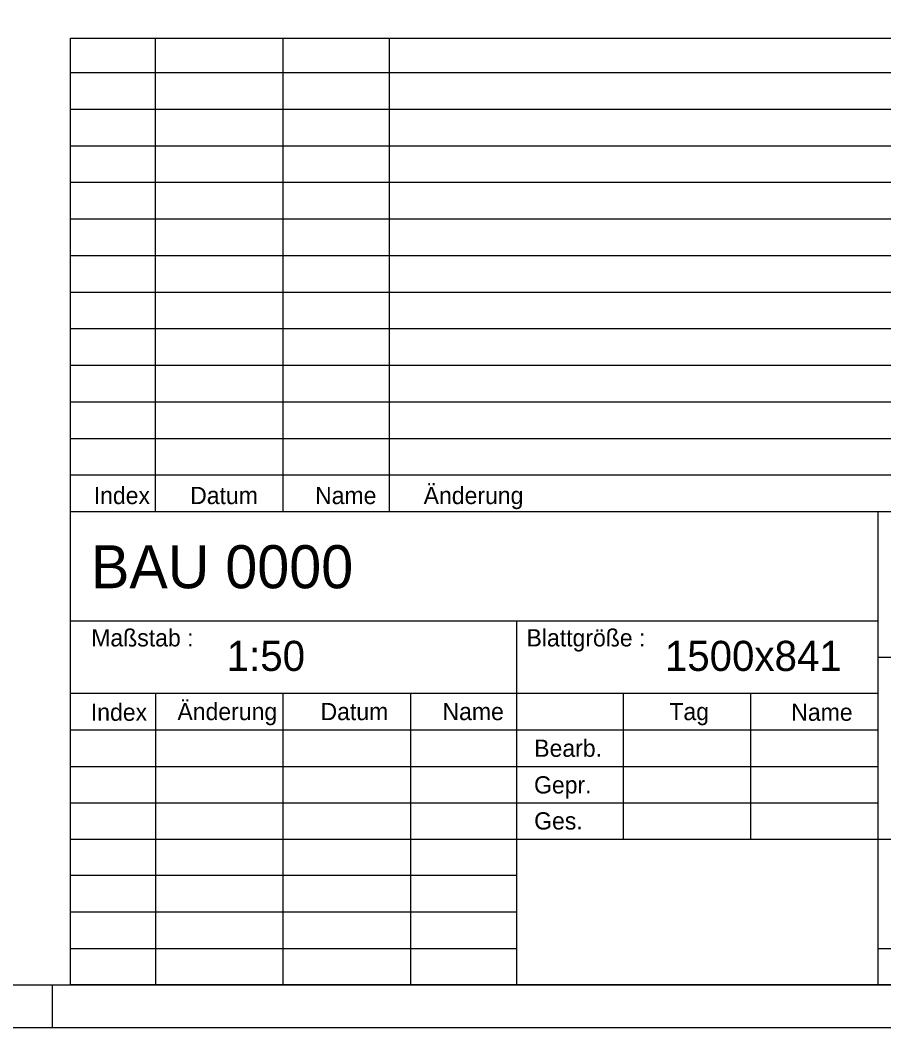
# Model space of a CAD drawing. Extents: x 0 to 75, y 0 to 42.1.
# Drawn here: x 65.56 to 70.58, y 0 to 5.85 of the extents above; entities that cross this region are included whole.
import ezdxf

# ---------------------------------------------------------------- set-up
doc = ezdxf.new("R2010")
doc.units = 0
doc.layers.add('90_Plankopf', color=7, linetype='Continuous')

msp = doc.modelspace()

# ---------------------------------------------------------------- linework, layer by layer
at = {"layer": '90_Plankopf'}
for p, q in [((65.856, 2.9995), (65.856, 5.749)), ((65.856, 5.749), (74.75, 5.749)), ((66.3501, 2.9995), (66.3501, 5.749)), ((67.0913, 2.9995), (67.0913, 5.749)), ((67.709, 2.9995), (67.709, 5.749)), ((65.856, 5.5495), (74.75, 5.5495)), ((65.856, 5.337), (74.75, 5.337)), ((65.856, 5.1245), (74.75, 5.1245)), ((65.856, 4.912), (74.75, 4.912)), ((65.856, 4.6995), (74.75, 4.6995)), ((65.856, 4.487), (74.75, 4.487)), ((65.856, 4.2745), (74.75, 4.2745)), ((65.856, 4.062), (74.75, 4.062)), ((65.856, 3.8495), (74.75, 3.8495)), ((65.856, 3.637), (74.75, 3.637)), ((65.856, 3.4245), (74.75, 3.4245)), ((65.856, 3.212), (74.75, 3.212)), ((65.856, 2.9995), (74.75, 2.9995)), ((65.856, 0.25), (65.856, 2.9995)), ((65.856, 2.9995), (74.75, 2.9995)), ((70.55, 0.25), (70.55, 2.9995)), ((65.856, 2.365), (70.55, 2.365)), ((68.4501, 0.25), (68.4501, 2.365)), ((70.55, 2.1535), (74.75, 2.1535)), ((65.856, 1.9435), (70.55, 1.9435)), ((66.3501, 1.942), (66.3501, 0.25)), ((67.0913, 0.25), (67.0913, 1.942)), ((67.8325, 0.25), (67.8325, 1.942)), ((69.0677, 1.942), (69.0677, 1.096)), ((69.8089, 1.096), (69.8089, 1.942)), ((65.856, 1.7315), (70.55, 1.7315)), ((65.856, 1.519), (70.55, 1.519)), ((65.856, 1.3075), (70.55, 1.3075)), ((65.856, 1.096), (70.55, 1.096)), ((65.856, 1.096), (70.55, 1.096)), ((68.4501, 1.096), (70.55, 1.096)), ((70.55, 1.096), (74.75, 1.096)), ((68.4501, 0.8845), (65.856, 0.8845)), ((68.4501, 0.673), (65.856, 0.673)), ((65.856, 0.4615), (68.4501, 0.4615)), ((70.55, 0.4615), (74.75, 0.4615)), ((65.75, 0), (65.75, 0.25)), ((74.75, 0.25), (65.856, 0.25)), ((65.856, 0.25), (68.4501, 0.25)), ((66.44, 0.25), (74.75, 0.25)), ((66.44, 0.25), (74.75, 0.25))]:
    msp.add_line(p, q, dxfattribs=at)
msp.add_lwpolyline([(0, 42.05), (75, 42.05), (75, 0), (0, 0)], close=True, dxfattribs=at)
msp.add_lwpolyline([(59.6038, 0.25), (74.75, 0.25), (74.75, 41.8), (59.6038, 41.8)], dxfattribs=at)

# ---------------------------------------------------------------- texts
for s, height, p in [('Änderung', 0.1, (67.9079, 3.0428)), ('Index', 0.1, (65.9902, 3.0428)), ('Datum', 0.1, (66.5507, 3.0428)), ('Name', 0.1, (67.2769, 3.0428)), ('BAU 0000      ', 0.25, (65.9745, 2.5538)), ('Maßstab :', 0.1, (65.9758, 2.2158)), ('Blattgröße :', 0.099995, (68.5058, 2.2158)), ('1:50     ', 0.175, (66.7631, 2.0734)), ('1500x841 ', 0.175, (69.31, 2.0734)), ('Index', 0.1, (65.9734, 1.7837)), ('Änderung', 0.1, (66.4767, 1.7875)), ('Datum', 0.1, (67.3084, 1.7875)), ('Name', 0.1, (68.0174, 1.7875)), ('Tag', 0.1, (69.3362, 1.7875)), ('Name', 0.1, (70.0446, 1.7837)), ('Bearb.', 0.1, (68.5507, 1.5745)), ('Gepr.', 0.1, (68.5495, 1.3615)), ('Ges.', 0.1, (68.5502, 1.1523))]:
    msp.add_text(s, height=height, dxfattribs=at).set_placement(p)

doc.saveas('drawing.dxf')
